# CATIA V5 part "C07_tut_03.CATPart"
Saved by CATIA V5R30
Part number: Part1
Bounding box of the stored display mesh (mm): x 0 to 108, y -52.5 to 52.5, z -52.5 to 52.5
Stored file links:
  D:\PROJECTS\CATIA V56R 2020\Resources\c07\C07_tut_03.CATPart
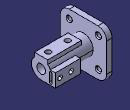
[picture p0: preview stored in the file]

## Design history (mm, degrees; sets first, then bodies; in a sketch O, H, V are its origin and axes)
Body1 (main body)
  Sketch1 on yz-plane, origin (0, 0, 0), H (0, 1, 0), V (0, 0, 1)
    line L1 (52.5, 32.5) -> (52.5, -32.5)
    line L2 (32.5, -52.5) -> (-32.5, -52.5)
    line L3 (-52.5, -32.5) -> (-52.5, 32.5)
    line L4 (-32.5, 52.5) -> (32.5, 52.5)
    point P1 (52.5, 52.5)
    point P2 (52.5, -52.5)
    point P3 (-52.5, -52.5)
    arc A1 centre (32.5, 32.5) radius 20 from (52.5, 32.5) to (32.5, 52.5) ccw
    arc A2 centre (32.5, -32.5) radius 20 from (52.5, -32.5) to (32.5, -52.5) cw
    arc A3 centre (-32.5, -32.5) radius 20 from (-32.5, -52.5) to (-52.5, -32.5) cw
    arc A4 centre (-32.5, 32.5) radius 20 from (-52.5, 32.5) to (-32.5, 52.5) cw
    distance P1 P2 = 105
    radius A1 = 20
    distance P2 P3 = 105
    radius A2 = 20
    radius A3 = 20
    radius A4 = 20
    vertical: L1 V, L3 V
    horizontal: L2 H, L4 H
    equidistance: L1 L3 O, L2 L4 O
    coincidence: L1 P1, L4 P1, L1 P2, L2 P2, L2 P3, L3 P3
    tangency: A1 L1, A1 L4, A2 L1, A2 L2, A3 L2, A3 L3, A4 L3, A4 L4
  Pad1: profile Sketch1, direction (1, 0, 0), length 12
  Sketch2 on face of Pad1, origin (12, 0, 0), H (0, 1, 0), V (0, 0, 1)
    circle A1 centre (0, 0) radius 22
    radius A1 = 22
  Pad2: profile Sketch2, direction (1, 0, 0), length 96
  Sketch3 on face of Pad2, origin (108, 0, 0), H (0, 1, 0), V (0, 0, 1)
    point P1 (-15, 16.0935)
    line L1 (-15, 16.0935) -> (-15, 25)
    line L2 (-15, 25) -> (15, 25)
    line L3 (15, 25) -> (15, 16.0935)
    point P4 (15, 16.0935)
    axis line L4 (0, 0) -> (0, 25)
    point P5 (0, 25)
    reference projected circle E1 centre (0, 0) radius 22 from edge [face of Pad2 | face of Pad2]
    reference projected circle E2 centre (0, 0) radius 22 from edge [face of Pad2 | face of Pad2]
    projected circle E3 centre (0, 0) radius 22 from edge [face of Pad2 | face of Pad2]
    projected arc E4 centre (0, 0) radius 22 from (15, 16.0935) to (-15, 16.0935) ccw from edge [face of Pad2 | face of Pad2]
    length L2 = 30
    distance H L2 = 25
    vertical: L1 V, L3 V, L4 V
    horizontal: L2 H
    midpoint: P5 L2
    coincidence: P4 E1, P1 E2
  Pad3: profile Sketch3, direction (-1, 0, 0), length 76
  Sketch4 on face of Pad2, origin (108, 0, 0), H (0, 1, 0), V (0, 0, 1)
    point P1 (0, -22)
    line L1 (0, -22) -> (32, -22)
    line L2 (32, -22) -> (32, 8)
    line L3 (32, 8) -> (20.4939, 8)
    point P4 (20.4939, 8)
    reference projected circle E1 centre (0, 0) radius 22 from edge of Pad2
    reference projected circle E2 centre (0, 0) radius 22 from edge [face of Pad2 | face of Pad2]
    reference projected circle E3 centre (0, 0) radius 22 from edge [face of Pad2 | face of Pad2]
    projected arc E4 centre (0, 0) radius 22 from (-15, 16.0935) to (15, 16.0935) ccw from edge of Pad3
    projected arc E5 centre (0, 0) radius 22 from (0, -22) to (20.4939, 8) ccw from edge of Pad3
    length L2 = 30
    distance V L2 = 32
    coincidence: P1 V, P4 E1, P1 E2
    horizontal: L1 H, L3 H
    vertical: L2 V
    tangency: L1 E3
  Pad4: profile Sketch4, direction (-1, 0, 0), length 57
  Sketch5 on face of Pad2, origin (108, 0, 0), H (0, 1, 0), V (0, 0, 1)
    line L1 (24.5, 2.5) -> (24.5, -16.5)
    line L2 (18.5, -16.5) -> (18.5, 2.5)
    point P4 (18.5, -16.5)
    arc A1 centre (21.5, 2.5) radius 3 from (24.5, 2.5) to (18.5, 2.5) ccw
    point P5 (21.5, 2.5)
    arc A2 centre (21.5, -16.5) radius 3 from (18.5, -16.5) to (24.5, -16.5) ccw
    point P6 (21.5, -16.5)
    point P7 (18.5, -16.5)
    reference projected line E1 (52.5, -32.5) -> (52.5, 32.5) from edge [face of Pad1 from Sketch1.L1 | end face of Pad1]
    reference projected line E2 (-32.5, -52.5) -> (32.5, -52.5) from edge [face of Pad1 from Sketch1.L2 | end face of Pad1]
    length L1 = 19
    distance L1 P5 = 3
    distance L2 E1 = 34
    distance P6 E2 = 36
    vertical: L1 V, L2 V
    tangency: A1 L1, A2 L1, A2 L2, A1 L2
    coincidence: P4 P7
  Pocket1: profile Sketch5, direction (-1, 0, 0), length 50
  Sketch6 on face of Pad2, origin (108, 0, 0), H (0, 1, 0), V (0, 0, 1)
    point P1 (0, 0)
    coincidence: P1 O
  Hole1: placed by Sketch6, at (108, 0, 0) direction (-1, 0, 0), diameter 20, up to end face of Pad1
  Sketch7 on face of Pad3, origin (90.7325, -5.9449, 25), H (1, 0, 0), V (0, 1, 0)
    point P1 (1.2675, 5.9449)
    reference projected line E1 (17.2675, -9.0551) -> (-58.7325, -9.0551) from edge [face of Pad3 | face of Pad3]
    reference projected line E2 (17.2675, 20.9449) -> (17.2675, -9.0551) from edge [face of Pad3 | face of Pad3]
    distance P1 E1 = 15
    distance P1 E2 = 16
  Hole2: placed by Sketch7, at (92, 0, 25) direction (0, 0, -1), diameter 12, depth 33.0037, threaded, thread diameter 13.2, thread depth 10, pitch 1
  RectPattern1: of Hole2, direction 1 instances 2, spacing 44, along edge [face of Pad3 | face of Pad3]
  Sketch8 on face of Pad4, origin (86.2721, 32, -2.7131), H (1, 0, 0), V (0, 0, -1)
    point P1 (10.7279, 4.2869)
    reference projected line E1 (21.7279, 19.2869) -> (-35.2721, 19.2869) from edge [face of Pad4 | face of Pad4]
    reference projected line E2 (21.7279, 19.2869) -> (21.7279, -10.7131) from edge [face of Pad4 | face of Pad4]
    distance P1 E1 = 15
    distance E2 P1 = 11
  Hole3: placed by Sketch8, at (97, 32, -7) direction (0, -1, 0), diameter 10, through (limit type 6)
  RectPattern2: of Hole3, direction 1 instances 2, spacing 25, along edge [face of Pad4 | face of Pad4], direction 2 instances 2, spacing 76
  Sketch9 on face of Pad1, origin (12, -36.1764, 22.8739), H (0, 1, 0), V (0, 0, 1)
    point P1 (3.6764, -55.3739)
    reference projected line E1 (-16.3236, 9.6261) -> (-16.3236, -55.3739) from edge [face of Pad1 | face of Pad1]
    reference projected line E2 (3.6764, -75.3739) -> (68.6764, -75.3739) from edge [face of Pad1 | face of Pad1]
    distance P1 E1 = 20
    distance E2 P1 = 20
  Hole4: placed by Sketch9, at (12, -32.5, -32.5) direction (-1, 0, 0), diameter 10, through (limit type 3), countersink depth 2, countersink angle 90
  RectPattern3: of Hole4, direction 1 instances 2, spacing 66, along edge [face of Pad1 | face of Pad1], direction 2 instances 2, spacing 66, along edge [face of Pad1 | face of Pad1] reversed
